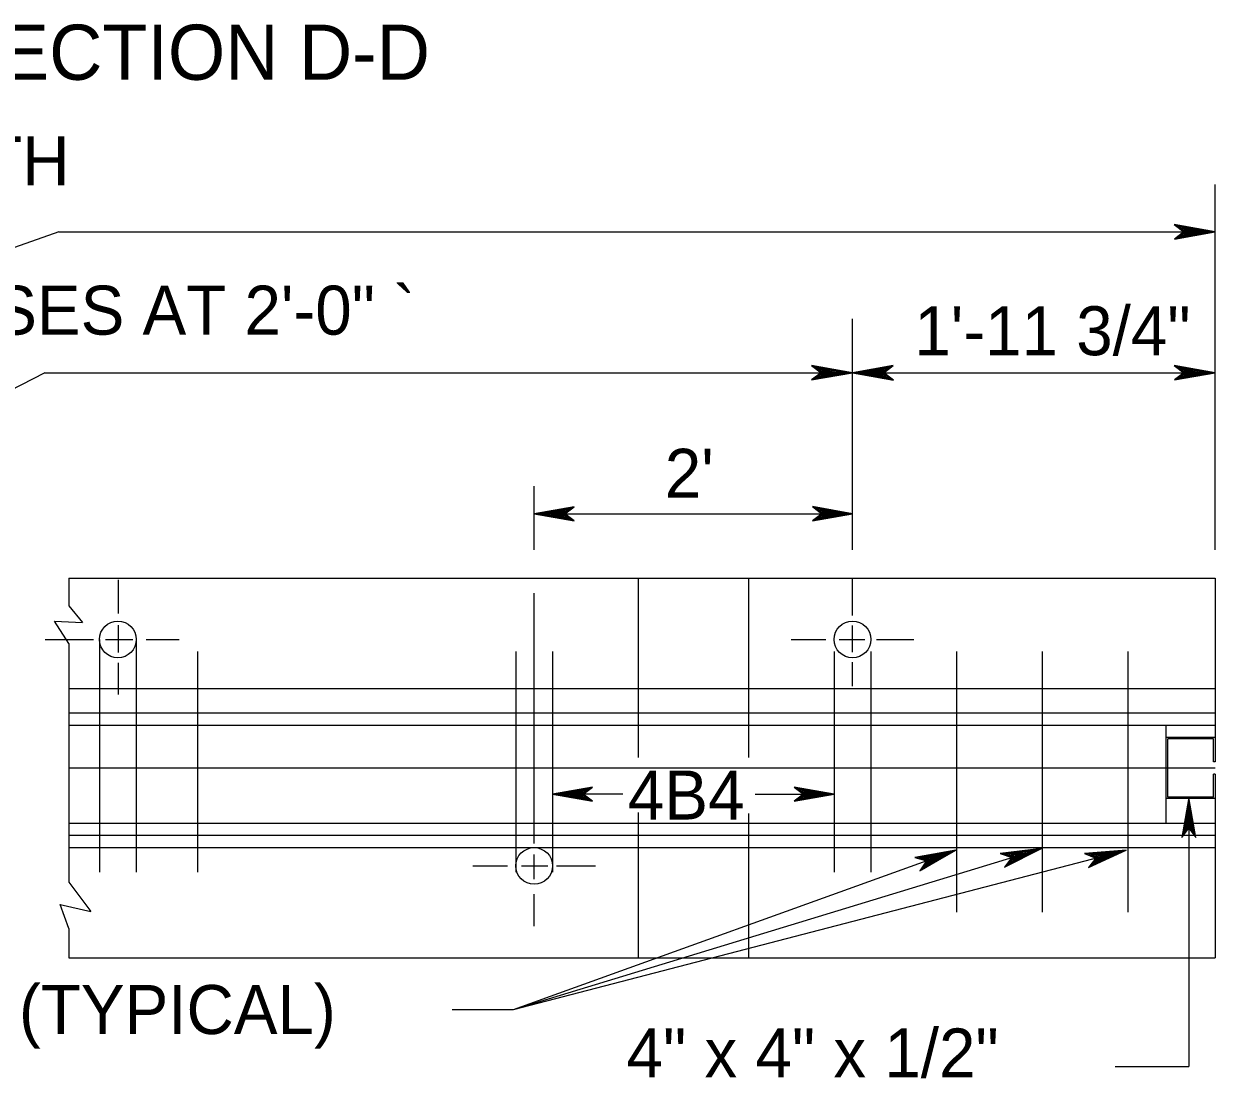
# Model space of a CAD drawing. Extents: x 499866 to 500993, y 499985 to 500645.
# Drawn here: x 500361.2 to 500458.5, y 500207.8 to 500293.8 of the extents above; entities that cross this region are included whole.
import ezdxf

# ---------------------------------------------------------------- set-up
doc = ezdxf.new("R2010")
doc.units = 0
doc.layers.add('24', color=7, linetype='Continuous')
doc.layers.add('5', color=7, linetype='Continuous')

msp = doc.modelspace()

# ---------------------------------------------------------------- linework, layer by layer
at = {"layer": '24'}
for points in [[(500458.452, 500276.846), (500455.102, 500277.438), (500455.903, 500276.846), (500455.12, 500276.263), (500458.452, 500276.846), (500458.23, 500276.84), (500455.196, 500277.394), (500455.965, 500276.839), (500455.255, 500276.309), (500458.11, 500276.83), (500457.998, 500276.846), (500455.4, 500277.308), (500455.983, 500276.839), (500455.383, 500276.385), (500457.947, 500276.846), (500457.836, 500276.83), (500455.564, 500277.24), (500456.006, 500276.846), (500455.555, 500276.438), (500457.512, 500276.829), (500457.324, 500276.83), (500455.733, 500277.155), (500456.042, 500276.856), (500455.709, 500276.523), (500457.29, 500276.846), (500457.111, 500276.857), (500455.915, 500277.061), (500456.145, 500276.829), (500455.896, 500276.6), (500456.947, 500276.846), (500456.778, 500276.863), (500456.059, 500277), (500456.178, 500276.839), (500455.982, 500276.66), (500456.69, 500276.846), (500456.222, 500276.958), (500456.29, 500276.83), (500456.084, 500276.701), (500456.573, 500276.829), (500456.265, 500276.906), (500456.394, 500276.805), (500456.246, 500276.745), (500456.393, 500276.839), (500456.316, 500276.856)], [(500428.85, 500265.346), (500425.5, 500265.938), (500426.301, 500265.346), (500425.518, 500264.763), (500428.85, 500265.346), (500428.628, 500265.34), (500425.594, 500265.894), (500426.363, 500265.339), (500425.653, 500264.809), (500428.508, 500265.33), (500428.396, 500265.346), (500425.798, 500265.808), (500426.381, 500265.339), (500425.781, 500264.885), (500428.345, 500265.346), (500428.234, 500265.33), (500425.962, 500265.74), (500426.404, 500265.346), (500425.953, 500264.938), (500427.91, 500265.329), (500427.721, 500265.33), (500426.131, 500265.655), (500426.44, 500265.356), (500426.107, 500265.023), (500427.688, 500265.346), (500427.509, 500265.357), (500426.313, 500265.561), (500426.543, 500265.329), (500426.294, 500265.1), (500427.345, 500265.346), (500427.176, 500265.363), (500426.457, 500265.5), (500426.576, 500265.339), (500426.38, 500265.16), (500427.088, 500265.346), (500426.62, 500265.458), (500426.688, 500265.33), (500426.482, 500265.201), (500426.97, 500265.329), (500426.663, 500265.406), (500426.792, 500265.305), (500426.644, 500265.245), (500426.791, 500265.339), (500426.714, 500265.356)], [(500428.85, 500265.346), (500432.2, 500264.754), (500431.4, 500265.346), (500432.183, 500265.929), (500428.85, 500265.346), (500429.073, 500265.352), (500432.107, 500264.798), (500431.338, 500265.353), (500432.048, 500265.883), (500429.193, 500265.363), (500429.304, 500265.346), (500431.903, 500264.884), (500431.32, 500265.353), (500431.92, 500265.808), (500429.356, 500265.346), (500429.467, 500265.363), (500431.739, 500264.952), (500431.297, 500265.346), (500431.748, 500265.755), (500429.79, 500265.363), (500429.979, 500265.363), (500431.57, 500265.037), (500431.261, 500265.337), (500431.594, 500265.67), (500430.013, 500265.346), (500430.192, 500265.336), (500431.388, 500265.131), (500431.158, 500265.363), (500431.407, 500265.592), (500430.356, 500265.346), (500430.525, 500265.329), (500431.243, 500265.192), (500431.125, 500265.353), (500431.321, 500265.532), (500430.613, 500265.346), (500431.081, 500265.235), (500431.013, 500265.363), (500431.219, 500265.491), (500430.73, 500265.363), (500431.038, 500265.286), (500430.909, 500265.387), (500431.057, 500265.448), (500430.91, 500265.353), (500430.987, 500265.337)], [(500458.452, 500265.346), (500455.102, 500265.938), (500455.903, 500265.346), (500455.12, 500264.763), (500458.452, 500265.346), (500458.23, 500265.34), (500455.196, 500265.894), (500455.965, 500265.339), (500455.255, 500264.809), (500458.11, 500265.33), (500457.998, 500265.346), (500455.4, 500265.808), (500455.983, 500265.339), (500455.383, 500264.885), (500457.947, 500265.346), (500457.836, 500265.33), (500455.564, 500265.74), (500456.006, 500265.346), (500455.555, 500264.938), (500457.512, 500265.329), (500457.324, 500265.33), (500455.733, 500265.655), (500456.042, 500265.356), (500455.709, 500265.023), (500457.29, 500265.346), (500457.111, 500265.357), (500455.915, 500265.561), (500456.145, 500265.329), (500455.896, 500265.1), (500456.947, 500265.346), (500456.778, 500265.363), (500456.059, 500265.5), (500456.178, 500265.339), (500455.982, 500265.16), (500456.69, 500265.346), (500456.222, 500265.458), (500456.29, 500265.33), (500456.084, 500265.201), (500456.573, 500265.329), (500456.265, 500265.406), (500456.394, 500265.305), (500456.246, 500265.245), (500456.393, 500265.339), (500456.316, 500265.356)], [(500402.87, 500253.846), (500406.145, 500253.267), (500405.362, 500253.846), (500406.128, 500254.416), (500402.87, 500253.846), (500403.088, 500253.852), (500406.053, 500253.31), (500405.301, 500253.853), (500405.995, 500254.371), (500403.205, 500253.862), (500403.314, 500253.846), (500405.854, 500253.395), (500405.284, 500253.853), (500405.87, 500254.297), (500403.364, 500253.846), (500403.473, 500253.862), (500405.693, 500253.462), (500405.261, 500253.846), (500405.702, 500254.245), (500403.789, 500253.863), (500403.974, 500253.862), (500405.529, 500253.544), (500405.226, 500253.837), (500405.552, 500254.162), (500404.007, 500253.846), (500404.181, 500253.836), (500405.35, 500253.636), (500405.126, 500253.863), (500405.369, 500254.087), (500404.342, 500253.846), (500404.507, 500253.83), (500405.209, 500253.696), (500405.094, 500253.853), (500405.285, 500254.028), (500404.593, 500253.846), (500405.051, 500253.737), (500404.984, 500253.862), (500405.185, 500253.988), (500404.708, 500253.863), (500405.008, 500253.787), (500404.882, 500253.886), (500405.027, 500253.946), (500404.883, 500253.853), (500404.958, 500253.837)], [(500428.85, 500253.846), (500425.576, 500254.425), (500426.359, 500253.846), (500425.594, 500253.277), (500428.85, 500253.846), (500428.633, 500253.84), (500425.668, 500254.382), (500426.42, 500253.839), (500425.726, 500253.322), (500428.516, 500253.83), (500428.407, 500253.846), (500425.867, 500254.298), (500426.437, 500253.84), (500425.851, 500253.395), (500428.357, 500253.846), (500428.248, 500253.83), (500426.028, 500254.231), (500426.46, 500253.846), (500426.019, 500253.447), (500427.932, 500253.83), (500427.747, 500253.83), (500426.193, 500254.148), (500426.495, 500253.856), (500426.169, 500253.53), (500427.714, 500253.846), (500427.539, 500253.856), (500426.37, 500254.056), (500426.595, 500253.83), (500426.352, 500253.606), (500427.379, 500253.846), (500427.214, 500253.863), (500426.512, 500253.997), (500426.628, 500253.839), (500426.436, 500253.664), (500427.128, 500253.846), (500426.671, 500253.955), (500426.737, 500253.83), (500426.536, 500253.704), (500427.013, 500253.83), (500426.713, 500253.905), (500426.839, 500253.806), (500426.694, 500253.747), (500426.838, 500253.839), (500426.763, 500253.856)], [(500404.369, 500230.961), (500407.643, 500230.382), (500406.861, 500230.961), (500407.626, 500231.531), (500404.369, 500230.961), (500404.587, 500230.967), (500407.552, 500230.425), (500406.8, 500230.968), (500407.494, 500231.486), (500404.704, 500230.977), (500404.813, 500230.961), (500407.353, 500230.509), (500406.783, 500230.968), (500407.369, 500231.412), (500404.863, 500230.96), (500404.972, 500230.977), (500407.192, 500230.576), (500406.76, 500230.96), (500407.201, 500231.36), (500405.288, 500230.977), (500405.472, 500230.977), (500407.027, 500230.659), (500406.725, 500230.951), (500407.051, 500231.277), (500405.506, 500230.961), (500405.68, 500230.95), (500406.849, 500230.751), (500406.624, 500230.977), (500406.868, 500231.201), (500405.841, 500230.961), (500406.006, 500230.944), (500406.708, 500230.81), (500406.592, 500230.968), (500406.783, 500231.143), (500406.092, 500230.96), (500406.549, 500230.852), (500406.483, 500230.977), (500406.684, 500231.102), (500406.207, 500230.977), (500406.507, 500230.902), (500406.381, 500231.001), (500406.526, 500231.06), (500406.382, 500230.968), (500406.457, 500230.951)], [(500427.352, 500230.961), (500424.078, 500231.539), (500424.86, 500230.961), (500424.095, 500230.391), (500427.352, 500230.961), (500427.134, 500230.955), (500424.169, 500231.497), (500424.921, 500230.954), (500424.227, 500230.436), (500427.017, 500230.945), (500426.908, 500230.961), (500424.368, 500231.412), (500424.938, 500230.954), (500424.352, 500230.51), (500426.858, 500230.961), (500426.749, 500230.945), (500424.529, 500231.345), (500424.961, 500230.961), (500424.52, 500230.562), (500426.433, 500230.944), (500426.248, 500230.945), (500424.694, 500231.263), (500424.996, 500230.97), (500424.671, 500230.645), (500426.216, 500230.961), (500426.041, 500230.971), (500424.872, 500231.171), (500425.096, 500230.944), (500424.853, 500230.72), (500425.88, 500230.961), (500425.715, 500230.977), (500425.013, 500231.112), (500425.129, 500230.954), (500424.937, 500230.779), (500425.63, 500230.961), (500425.172, 500231.07), (500425.238, 500230.945), (500425.037, 500230.819), (500425.514, 500230.944), (500425.214, 500231.019), (500425.34, 500230.921), (500425.195, 500230.862), (500425.339, 500230.954), (500425.264, 500230.97)], [(500456.305, 500230.688), (500455.726, 500227.413), (500456.305, 500228.196), (500456.874, 500227.43), (500456.305, 500230.688), (500456.311, 500230.47), (500455.769, 500227.505), (500456.312, 500228.257), (500456.83, 500227.563), (500456.321, 500230.353), (500456.305, 500230.244), (500455.853, 500227.704), (500456.311, 500228.274), (500456.756, 500227.688), (500456.304, 500230.194), (500456.321, 500230.085), (500455.92, 500227.865), (500456.304, 500228.297), (500456.704, 500227.856), (500456.321, 500229.769), (500456.321, 500229.584), (500456.003, 500228.03), (500456.295, 500228.332), (500456.621, 500228.007), (500456.305, 500229.551), (500456.295, 500229.377), (500456.095, 500228.208), (500456.321, 500228.432), (500456.545, 500228.189), (500456.305, 500229.216), (500456.288, 500229.051), (500456.154, 500228.349), (500456.312, 500228.465), (500456.487, 500228.273), (500456.304, 500228.966), (500456.196, 500228.508), (500456.321, 500228.574), (500456.447, 500228.373), (500456.321, 500228.85), (500456.246, 500228.55), (500456.345, 500228.676), (500456.404, 500228.531), (500456.312, 500228.675), (500456.295, 500228.6)], [(500437.299, 500226.376), (500433.947, 500225.799), (500434.9, 500225.513), (500434.361, 500224.699), (500437.299, 500226.376), (500437.092, 500226.295), (500434.05, 500225.789), (500434.961, 500225.527), (500434.472, 500224.788), (500436.983, 500226.245), (500436.872, 500226.222), (500434.27, 500225.777), (500434.978, 500225.533), (500434.568, 500224.903), (500436.824, 500226.205), (500436.725, 500226.152), (500434.449, 500225.769), (500434.997, 500225.548), (500434.711, 500225.011), (500436.421, 500226.042), (500436.242, 500225.978), (500434.636, 500225.746), (500435.028, 500225.569), (500434.827, 500225.143), (500436.205, 500225.982), (500436.033, 500225.932), (500434.839, 500225.719), (500435.134, 500225.579), (500434.977, 500225.279), (500435.882, 500225.866), (500435.718, 500225.825), (500434.995, 500225.711), (500435.161, 500225.599), (500435.038, 500225.365), (500435.641, 500225.78), (500435.162, 500225.726), (500435.27, 500225.628), (500435.12, 500225.438), (500435.536, 500225.723), (500435.221, 500225.692), (500435.376, 500225.64), (500435.258, 500225.533), (500435.364, 500225.672), (500435.286, 500225.662)], [(500444.282, 500226.525), (500440.906, 500226.114), (500441.844, 500225.781), (500441.265, 500224.995), (500444.282, 500226.525), (500444.072, 500226.454), (500441.008, 500226.099), (500441.906, 500225.793), (500441.381, 500225.078), (500443.96, 500226.409), (500443.848, 500226.392), (500441.228, 500226.076), (500441.922, 500225.798), (500441.481, 500225.188), (500443.799, 500226.378), (500443.698, 500226.329), (500441.405, 500226.059), (500441.943, 500225.812), (500441.63, 500225.289), (500443.388, 500226.235), (500443.207, 500226.18), (500441.591, 500226.027), (500441.974, 500225.831), (500441.753, 500225.415), (500443.17, 500226.186), (500442.996, 500226.144), (500441.793, 500225.99), (500442.08, 500225.836), (500441.909, 500225.544), (500442.842, 500226.086), (500442.676, 500226.053), (500441.949, 500225.974), (500442.109, 500225.855), (500441.974, 500225.626), (500442.597, 500226.011), (500442.116, 500225.981), (500442.219, 500225.878), (500442.059, 500225.695), (500442.489, 500225.96), (500442.173, 500225.944), (500442.325, 500225.885), (500442.202, 500225.784), (500442.315, 500225.917), (500442.237, 500225.911)], [(500451.191, 500226.376), (500447.8, 500226.107), (500448.723, 500225.735), (500448.112, 500224.973), (500451.191, 500226.376), (500450.977, 500226.314), (500447.902, 500226.088), (500448.785, 500225.743), (500448.231, 500225.052), (500450.864, 500226.274), (500450.751, 500226.262), (500448.12, 500226.055), (500448.802, 500225.748), (500448.337, 500225.157), (500450.702, 500226.249), (500450.598, 500226.205), (500448.297, 500226.031), (500448.823, 500225.761), (500448.49, 500225.252), (500450.285, 500226.123), (500450.102, 500226.076), (500448.481, 500225.991), (500448.856, 500225.779), (500448.617, 500225.373), (500450.066, 500226.084), (500449.89, 500226.049), (500448.681, 500225.946), (500448.962, 500225.779), (500448.778, 500225.495), (500449.734, 500225.997), (500449.566, 500225.971), (500448.836, 500225.923), (500448.991, 500225.797), (500448.847, 500225.575), (500449.485, 500225.933), (500449.004, 500225.923), (500449.102, 500225.816), (500448.935, 500225.64), (500449.376, 500225.887), (500449.059, 500225.884), (500449.209, 500225.819), (500449.081, 500225.723), (500449.199, 500225.851), (500449.121, 500225.848)]]:
    msp.add_lwpolyline(points, dxfattribs=at)
at = {"layer": '5'}
for p, q in [((500458.452, 500250.901), (500458.452, 500280.714)), ((500364.068, 500276.846), (500357.684, 500274.611)), ((500364.068, 500276.846), (500458.452, 500276.846)), ((500428.85, 500250.901), (500428.85, 500269.762)), ((500362.928, 500265.346), (500358.368, 500263.012)), ((500362.928, 500265.346), (500428.85, 500265.346)), ((500428.85, 500265.346), (500458.452, 500265.346)), ((500402.87, 500250.901), (500402.87, 500256.087)), ((500402.87, 500253.846), (500428.85, 500253.846)), ((500364.899, 500248.583), (500458.452, 500248.583)), ((500364.899, 500248.583), (500364.899, 500246.341)), ((500368.943, 500245.69), (500368.943, 500248.452)), ((500411.364, 500248.583), (500411.364, 500233.959)), ((500420.357, 500248.583), (500420.357, 500233.959)), ((500428.85, 500245.546), (500428.85, 500248.583)), ((500458.452, 500248.583), (500458.452, 500233.594)), ((500402.87, 500226.927), (500402.87, 500247.367)), ((500364.899, 500246.341), (500366.006, 500244.972)), ((500364.899, 500243.262), (500363.726, 500245.087)), ((500363.726, 500245.087), (500366.006, 500244.972)), ((500368.943, 500242.52), (500368.943, 500244.761)), ((500428.85, 500242.536), (500428.85, 500244.714)), ((500362.966, 500243.587), (500366.905, 500243.587)), ((500364.899, 500243.262), (500364.899, 500223.767)), ((500367.397, 500243.587), (500367.397, 500224.601)), ((500367.897, 500243.587), (500370.106, 500243.587)), ((500370.395, 500243.587), (500370.395, 500224.601)), ((500371.195, 500243.587), (500373.893, 500243.587)), ((500423.854, 500243.587), (500426.683, 500243.587)), ((500427.772, 500243.587), (500429.853, 500243.587)), ((500428.85, 500243.587), (500428.85, 500243.587)), ((500430.813, 500243.587), (500433.847, 500243.587)), ((500375.391, 500242.588), (500375.391, 500224.601)), ((500401.371, 500242.588), (500401.371, 500224.601)), ((500404.369, 500242.588), (500404.369, 500224.601)), ((500427.352, 500242.588), (500427.352, 500224.601)), ((500430.35, 500242.588), (500430.35, 500224.601)), ((500437.344, 500242.588), (500437.344, 500221.328)), ((500444.339, 500242.588), (500444.339, 500221.328)), ((500451.334, 500242.588), (500451.334, 500221.328)), ((500368.943, 500239.094), (500368.943, 500241.688)), ((500428.85, 500239.78), (500428.85, 500241.736)), ((500364.899, 500239.59), (500458.452, 500239.59)), ((500364.899, 500237.592), (500458.452, 500237.592)), ((500364.899, 500236.592), (500458.452, 500236.592)), ((500454.456, 500228.598), (500454.456, 500236.592)), ((500458.452, 500235.593), (500454.456, 500235.593)), ((500458.328, 500235.468), (500454.58, 500235.468)), ((500454.58, 500230.722), (500454.58, 500235.468)), ((500458.328, 500233.594), (500458.328, 500235.468)), ((500458.452, 500233.594), (500458.328, 500233.594)), ((500364.899, 500233.095), (500458.452, 500233.095)), ((500458.452, 500232.595), (500458.328, 500232.595)), ((500458.328, 500230.722), (500458.328, 500232.595)), ((500458.452, 500232.595), (500458.452, 500217.607)), ((500410.114, 500230.961), (500404.369, 500230.961)), ((500420.917, 500230.961), (500427.352, 500230.961)), ((500458.452, 500230.597), (500454.456, 500230.597)), ((500458.328, 500230.722), (500454.58, 500230.722)), ((500456.305, 500230.688), (500456.305, 500208.745)), ((500411.364, 500229.463), (500411.364, 500217.607)), ((500420.357, 500229.391), (500420.357, 500217.607)), ((500364.899, 500228.598), (500458.452, 500228.598)), ((500364.899, 500227.599), (500458.452, 500227.599)), ((500364.899, 500226.6), (500458.452, 500226.6)), ((500401.182, 500213.381), (500444.282, 500226.525)), ((500401.182, 500213.381), (500437.299, 500226.376)), ((500402.87, 500224.013), (500402.87, 500226.031)), ((500397.874, 500225.101), (500400.684, 500225.101)), ((500401.837, 500225.101), (500403.982, 500225.101)), ((500404.686, 500225.101), (500407.866, 500225.101)), ((500364.899, 500223.767), (500366.69, 500221.373)), ((500402.87, 500220.193), (500402.87, 500222.797)), ((500364.899, 500220.005), (500364.182, 500221.943)), ((500364.182, 500221.943), (500366.69, 500221.373)), ((500364.899, 500220.005), (500364.899, 500217.607)), ((500364.899, 500217.607), (500458.452, 500217.607)), ((500450.277, 500208.745), (500456.305, 500208.745))]:
    msp.add_line(p, q, dxfattribs=at)
msp.add_lwpolyline([(500396.186, 500213.381), (500401.182, 500213.381), (500451.191, 500226.376)], dxfattribs=at)
for centre in [(500368.896, 500243.587), (500428.851, 500243.587), (500402.87, 500225.101)]:
    msp.add_circle(centre, 1.499, dxfattribs=at)

# ---------------------------------------------------------------- texts
for s, height, p in [('SECTION D-D', 4.5, (500355.256, 500289.26)), ('NOMINAL LENGTH', 4, (500317.397, 500280.633)), ('9-ANCHOR RECESSES AT 2\'-0" `', 4, (500310.868, 500268.459)), ('1\'-11 3/4"', 4, (500433.898, 500266.778)), ("2'", 4, (500413.533, 500255.144)), ('4B4', 4, (500410.516, 500228.889)), ('STIRRUPS (TYPICAL)', 4, (500332.293, 500211.381)), ('4" x 4" x 1/2"', 4, (500410.412, 500207.837))]:
    msp.add_text(s, height=height, dxfattribs=at).set_placement(p)

doc.saveas('drawing.dxf')
